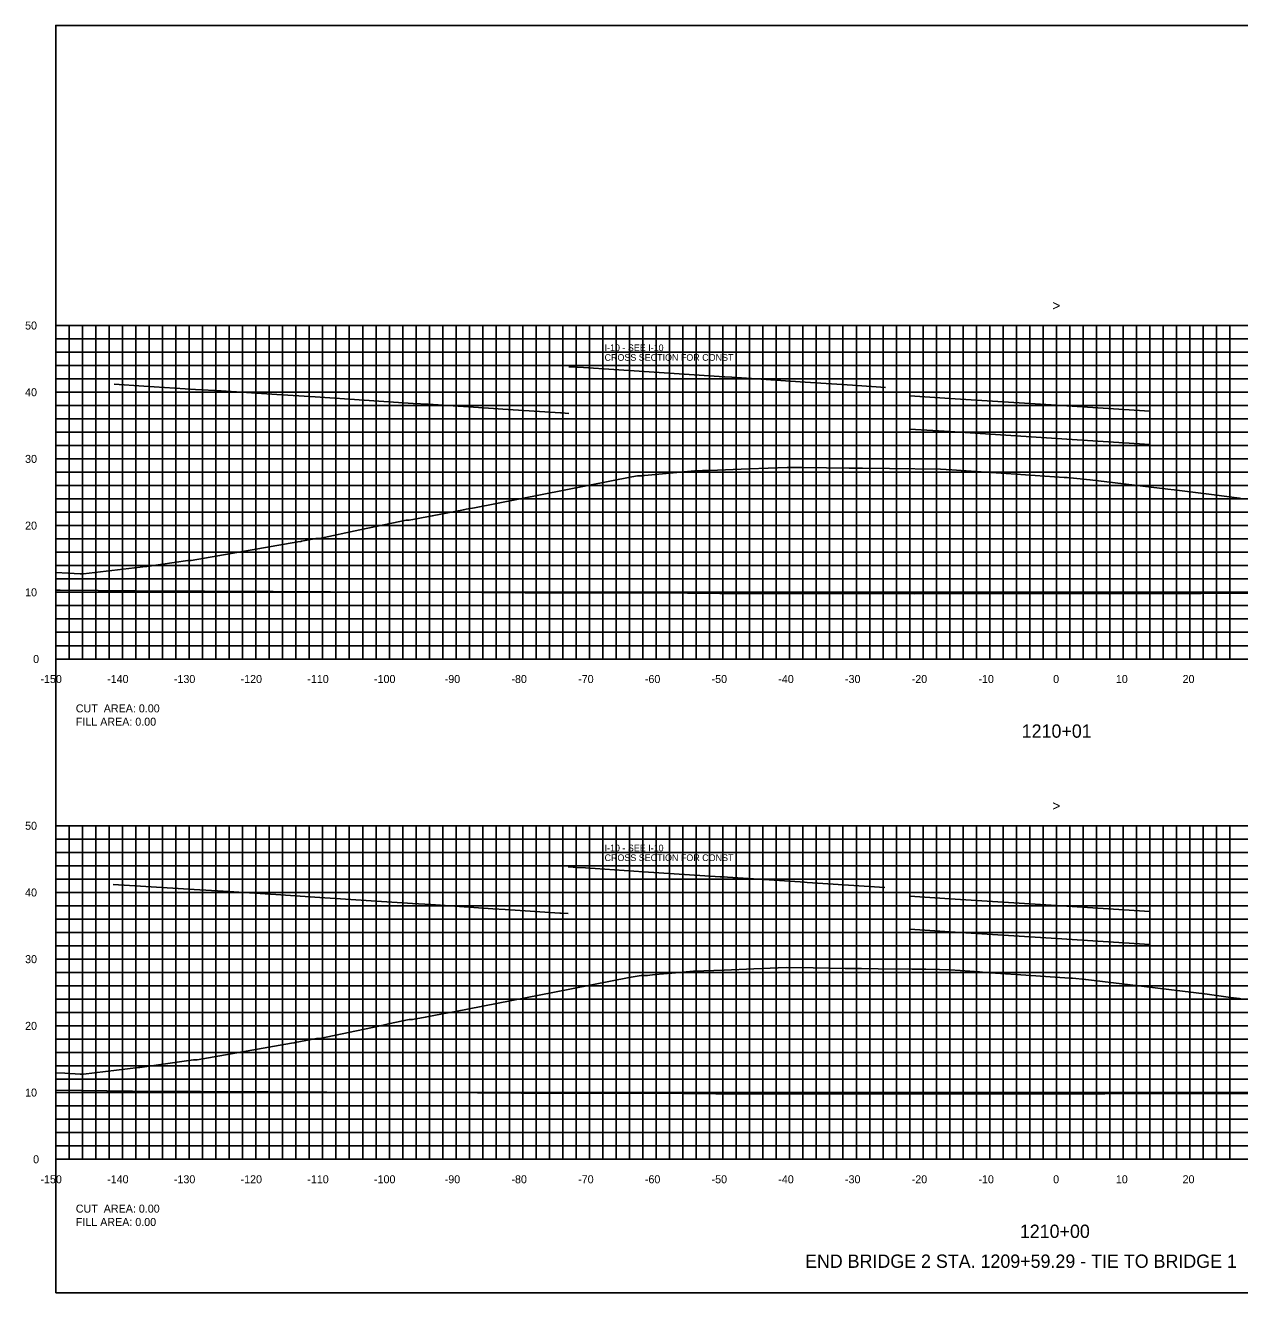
# Model space of a CAD drawing. Extents: x 1797305 to 1804485, y 245831 to 250849.
# Drawn here: x 1803836.4 to 1804018.5, y 250079.4 to 250269.4 of the extents above; entities that cross this region are included whole.
import ezdxf

# ---------------------------------------------------------------- set-up
doc = ezdxf.new("R2010")
doc.units = 0
for name, color, linetype in [('1', 7, 'Continuous'), ('10', 7, 'Continuous'), ('29', 7, 'Continuous'), ('60', 7, 'Continuous'), ('CL-CNST', 7, 'Continuous'), ('EDPV-LINE', 7, 'Continuous'), ('Level 31', 7, 'Continuous'), ('LIMT-CSLINE', 7, 'Continuous'), ('M-ROADS', 7, 'Continuous'), ('SURVEY - DRAINAGE - Area Shapes', 7, 'Continuous')]:
    doc.layers.add(name, color=color, linetype=linetype)

msp = doc.modelspace()

# ---------------------------------------------------------------- linework, layer by layer
msp.add_lwpolyline([(1803841, 250079.43), (1804141, 250079.43), (1804141, 250269.43), (1803841, 250269.43)], close=True)
at = {"layer": '29'}
for p, q in [((1803841, 250224.43), (1804141, 250224.43)), ((1803841, 250174.43), (1803841, 250224.43)), ((1803843, 250174.43), (1803843, 250224.43)), ((1803845, 250174.43), (1803845, 250224.43)), ((1803847, 250174.43), (1803847, 250224.43)), ((1803849, 250174.43), (1803849, 250224.43)), ((1803851, 250174.43), (1803851, 250224.43)), ((1803853, 250174.43), (1803853, 250224.43)), ((1803855, 250174.43), (1803855, 250224.43)), ((1803857, 250174.43), (1803857, 250224.43)), ((1803859, 250174.43), (1803859, 250224.43)), ((1803861, 250174.43), (1803861, 250224.43)), ((1803863, 250174.43), (1803863, 250224.43)), ((1803865, 250174.43), (1803865, 250224.43)), ((1803867, 250174.43), (1803867, 250224.43)), ((1803869, 250174.43), (1803869, 250224.43)), ((1803871, 250174.43), (1803871, 250224.43)), ((1803873, 250174.43), (1803873, 250224.43)), ((1803875, 250174.43), (1803875, 250224.43)), ((1803877, 250174.43), (1803877, 250224.43)), ((1803879, 250174.43), (1803879, 250224.43)), ((1803881, 250174.43), (1803881, 250224.43)), ((1803883, 250174.43), (1803883, 250224.43)), ((1803885, 250174.43), (1803885, 250224.43)), ((1803887, 250174.43), (1803887, 250224.43)), ((1803889, 250174.43), (1803889, 250224.43)), ((1803891, 250174.43), (1803891, 250224.43)), ((1803893, 250174.43), (1803893, 250224.43)), ((1803895, 250174.43), (1803895, 250224.43)), ((1803897, 250174.43), (1803897, 250224.43)), ((1803899, 250174.43), (1803899, 250224.43)), ((1803901, 250174.43), (1803901, 250224.43)), ((1803903, 250174.43), (1803903, 250224.43)), ((1803905, 250174.43), (1803905, 250224.43)), ((1803907, 250174.43), (1803907, 250224.43)), ((1803909, 250174.43), (1803909, 250224.43)), ((1803911, 250174.43), (1803911, 250224.43)), ((1803913, 250174.43), (1803913, 250224.43)), ((1803915, 250174.43), (1803915, 250224.43)), ((1803917, 250174.43), (1803917, 250224.43)), ((1803919, 250174.43), (1803919, 250224.43)), ((1803921, 250174.43), (1803921, 250224.43)), ((1803923, 250174.43), (1803923, 250224.43)), ((1803925, 250174.43), (1803925, 250224.43)), ((1803927, 250174.43), (1803927, 250224.43)), ((1803929, 250174.43), (1803929, 250224.43)), ((1803931, 250174.43), (1803931, 250224.43)), ((1803933, 250174.43), (1803933, 250224.43)), ((1803935, 250174.43), (1803935, 250224.43)), ((1803937, 250174.43), (1803937, 250224.43)), ((1803939, 250174.43), (1803939, 250224.43)), ((1803941, 250174.43), (1803941, 250224.43)), ((1803943, 250174.43), (1803943, 250224.43)), ((1803945, 250174.43), (1803945, 250224.43)), ((1803947, 250174.43), (1803947, 250224.43)), ((1803949, 250174.43), (1803949, 250224.43)), ((1803951, 250174.43), (1803951, 250224.43)), ((1803953, 250174.43), (1803953, 250224.43)), ((1803955, 250174.43), (1803955, 250224.43)), ((1803957, 250174.43), (1803957, 250224.43)), ((1803959, 250174.43), (1803959, 250224.43)), ((1803961, 250174.43), (1803961, 250224.43)), ((1803963, 250174.43), (1803963, 250224.43)), ((1803965, 250174.43), (1803965, 250224.43)), ((1803967, 250174.43), (1803967, 250224.43)), ((1803969, 250174.43), (1803969, 250224.43)), ((1803971, 250174.43), (1803971, 250224.43)), ((1803973, 250174.43), (1803973, 250224.43)), ((1803975, 250174.43), (1803975, 250224.43)), ((1803977, 250174.43), (1803977, 250224.43)), ((1803979, 250174.43), (1803979, 250224.43)), ((1803981, 250174.43), (1803981, 250224.43)), ((1803983, 250174.43), (1803983, 250224.43)), ((1803985, 250174.43), (1803985, 250224.43)), ((1803987, 250174.43), (1803987, 250224.43)), ((1803989, 250174.43), (1803989, 250224.43)), ((1803991, 250174.43), (1803991, 250224.43)), ((1803993, 250174.43), (1803993, 250224.43)), ((1803995, 250174.43), (1803995, 250224.43)), ((1803997, 250174.43), (1803997, 250224.43)), ((1803999, 250174.43), (1803999, 250224.43)), ((1804001, 250174.43), (1804001, 250224.43)), ((1804003, 250174.43), (1804003, 250224.43)), ((1804005, 250174.43), (1804005, 250224.43)), ((1804007, 250174.43), (1804007, 250224.43)), ((1804009, 250174.43), (1804009, 250224.43)), ((1804011, 250174.43), (1804011, 250224.43)), ((1804013, 250174.43), (1804013, 250224.43)), ((1804015, 250174.43), (1804015, 250224.43)), ((1804017, 250174.43), (1804017, 250224.43)), ((1803841, 250222.43), (1804141, 250222.43)), ((1803841, 250220.43), (1804141, 250220.43)), ((1803841, 250218.43), (1804141, 250218.43)), ((1803841, 250216.43), (1804141, 250216.43)), ((1803841, 250214.43), (1804141, 250214.43)), ((1803841, 250212.43), (1804141, 250212.43)), ((1803841, 250210.43), (1804141, 250210.43)), ((1803841, 250208.43), (1804141, 250208.43)), ((1803841, 250206.43), (1804141, 250206.43)), ((1803841, 250204.43), (1804141, 250204.43)), ((1803841, 250202.43), (1804141, 250202.43)), ((1803841, 250200.43), (1804141, 250200.43)), ((1803841, 250198.43), (1804141, 250198.43)), ((1803841, 250196.43), (1804141, 250196.43)), ((1803841, 250194.43), (1804141, 250194.43)), ((1803841, 250192.43), (1804141, 250192.43)), ((1803841, 250190.43), (1804141, 250190.43)), ((1803841, 250188.43), (1804141, 250188.43)), ((1803841, 250186.43), (1804141, 250186.43)), ((1803841, 250184.43), (1804141, 250184.43)), ((1803841, 250182.43), (1804141, 250182.43)), ((1803841, 250180.43), (1804141, 250180.43)), ((1803841, 250178.43), (1804141, 250178.43)), ((1803841, 250176.43), (1804141, 250176.43)), ((1803841, 250174.43), (1804141, 250174.43)), ((1803841, 250149.43), (1804141, 250149.43)), ((1803841, 250099.43), (1803841, 250149.43)), ((1803843, 250099.43), (1803843, 250149.43)), ((1803845, 250099.43), (1803845, 250149.43)), ((1803847, 250099.43), (1803847, 250149.43)), ((1803849, 250099.43), (1803849, 250149.43)), ((1803851, 250099.43), (1803851, 250149.43)), ((1803853, 250099.43), (1803853, 250149.43)), ((1803855, 250099.43), (1803855, 250149.43)), ((1803857, 250099.43), (1803857, 250149.43)), ((1803859, 250099.43), (1803859, 250149.43)), ((1803861, 250099.43), (1803861, 250149.43)), ((1803863, 250099.43), (1803863, 250149.43)), ((1803865, 250099.43), (1803865, 250149.43)), ((1803867, 250099.43), (1803867, 250149.43)), ((1803869, 250099.43), (1803869, 250149.43)), ((1803871, 250099.43), (1803871, 250149.43)), ((1803873, 250099.43), (1803873, 250149.43)), ((1803875, 250099.43), (1803875, 250149.43)), ((1803877, 250099.43), (1803877, 250149.43)), ((1803879, 250099.43), (1803879, 250149.43)), ((1803881, 250099.43), (1803881, 250149.43)), ((1803883, 250099.43), (1803883, 250149.43)), ((1803885, 250099.43), (1803885, 250149.43)), ((1803887, 250099.43), (1803887, 250149.43)), ((1803889, 250099.43), (1803889, 250149.43)), ((1803891, 250099.43), (1803891, 250149.43)), ((1803893, 250099.43), (1803893, 250149.43)), ((1803895, 250099.43), (1803895, 250149.43)), ((1803897, 250099.43), (1803897, 250149.43)), ((1803899, 250099.43), (1803899, 250149.43)), ((1803901, 250099.43), (1803901, 250149.43)), ((1803903, 250099.43), (1803903, 250149.43)), ((1803905, 250099.43), (1803905, 250149.43)), ((1803907, 250099.43), (1803907, 250149.43)), ((1803909, 250099.43), (1803909, 250149.43)), ((1803911, 250099.43), (1803911, 250149.43)), ((1803913, 250099.43), (1803913, 250149.43)), ((1803915, 250099.43), (1803915, 250149.43)), ((1803917, 250099.43), (1803917, 250149.43)), ((1803919, 250099.43), (1803919, 250149.43)), ((1803921, 250099.43), (1803921, 250149.43)), ((1803923, 250099.43), (1803923, 250149.43)), ((1803925, 250099.43), (1803925, 250149.43)), ((1803927, 250099.43), (1803927, 250149.43)), ((1803929, 250099.43), (1803929, 250149.43)), ((1803931, 250099.43), (1803931, 250149.43)), ((1803933, 250099.43), (1803933, 250149.43)), ((1803935, 250099.43), (1803935, 250149.43)), ((1803937, 250099.43), (1803937, 250149.43)), ((1803939, 250099.43), (1803939, 250149.43)), ((1803941, 250099.43), (1803941, 250149.43)), ((1803943, 250099.43), (1803943, 250149.43)), ((1803945, 250099.43), (1803945, 250149.43)), ((1803947, 250099.43), (1803947, 250149.43)), ((1803949, 250099.43), (1803949, 250149.43)), ((1803951, 250099.43), (1803951, 250149.43)), ((1803953, 250099.43), (1803953, 250149.43)), ((1803955, 250099.43), (1803955, 250149.43)), ((1803957, 250099.43), (1803957, 250149.43)), ((1803959, 250099.43), (1803959, 250149.43)), ((1803961, 250099.43), (1803961, 250149.43)), ((1803963, 250099.43), (1803963, 250149.43)), ((1803965, 250099.43), (1803965, 250149.43)), ((1803967, 250099.43), (1803967, 250149.43)), ((1803969, 250099.43), (1803969, 250149.43)), ((1803971, 250099.43), (1803971, 250149.43)), ((1803973, 250099.43), (1803973, 250149.43)), ((1803975, 250099.43), (1803975, 250149.43)), ((1803977, 250099.43), (1803977, 250149.43)), ((1803979, 250099.43), (1803979, 250149.43)), ((1803981, 250099.43), (1803981, 250149.43)), ((1803983, 250099.43), (1803983, 250149.43)), ((1803985, 250099.43), (1803985, 250149.43)), ((1803987, 250099.43), (1803987, 250149.43)), ((1803989, 250099.43), (1803989, 250149.43)), ((1803991, 250099.43), (1803991, 250149.43)), ((1803993, 250099.43), (1803993, 250149.43)), ((1803995, 250099.43), (1803995, 250149.43)), ((1803997, 250099.43), (1803997, 250149.43)), ((1803999, 250099.43), (1803999, 250149.43)), ((1804001, 250099.43), (1804001, 250149.43)), ((1804003, 250099.43), (1804003, 250149.43)), ((1804005, 250099.43), (1804005, 250149.43)), ((1804007, 250099.43), (1804007, 250149.43)), ((1804009, 250099.43), (1804009, 250149.43)), ((1804011, 250099.43), (1804011, 250149.43)), ((1804013, 250099.43), (1804013, 250149.43)), ((1804015, 250099.43), (1804015, 250149.43)), ((1804017, 250099.43), (1804017, 250149.43)), ((1803841, 250147.43), (1804141, 250147.43)), ((1803841, 250145.43), (1804141, 250145.43)), ((1803841, 250143.43), (1804141, 250143.43)), ((1803841, 250141.43), (1804141, 250141.43)), ((1803841, 250139.43), (1804141, 250139.43)), ((1803841, 250137.43), (1804141, 250137.43)), ((1803841, 250135.43), (1804141, 250135.43)), ((1803841, 250133.43), (1804141, 250133.43)), ((1803841, 250131.43), (1804141, 250131.43)), ((1803841, 250129.43), (1804141, 250129.43)), ((1803841, 250127.43), (1804141, 250127.43)), ((1803841, 250125.43), (1804141, 250125.43)), ((1803841, 250123.43), (1804141, 250123.43)), ((1803841, 250121.43), (1804141, 250121.43)), ((1803841, 250119.43), (1804141, 250119.43)), ((1803841, 250117.43), (1804141, 250117.43)), ((1803841, 250115.43), (1804141, 250115.43)), ((1803841, 250113.43), (1804141, 250113.43)), ((1803841, 250111.43), (1804141, 250111.43)), ((1803841, 250109.43), (1804141, 250109.43)), ((1803841, 250107.43), (1804141, 250107.43)), ((1803841, 250105.43), (1804141, 250105.43)), ((1803841, 250103.43), (1804141, 250103.43)), ((1803841, 250101.43), (1804141, 250101.43)), ((1803841, 250099.43), (1804141, 250099.43))]:
    msp.add_line(p, q, dxfattribs=at)
at = {"layer": 'CL-CNST'}
for points in [[(1803917.91, 250218.25), (1803918.04, 250218.24), (1803919.17, 250218.17), (1803920.09, 250218.12), (1803929.21, 250217.52), (1803941.2, 250216.74), (1803941.26, 250216.74), (1803941.31, 250216.74), (1803942.32, 250216.67), (1803953.31, 250215.95), (1803960.4, 250215.48), (1803965.36, 250215.15)], [(1803849.77, 250215.62), (1803854.19, 250215.35), (1803861.93, 250214.85), (1803865.79, 250214.62), (1803874.15, 250214.07), (1803879.88, 250213.73), (1803894.56, 250212.76), (1803896.82, 250212.63), (1803906.61, 250211.98), (1803908.03, 250211.9), (1803916.65, 250211.32), (1803916.79, 250211.32), (1803917.91, 250211.24)], [(1803969, 250213.87), (1803975, 250213.49), (1803991, 250212.47), (1804005, 250211.57)], [(1803841, 250184.77), (1803841.64, 250184.77), (1803853.04, 250184.66), (1803873.57, 250184.55), (1803882.2, 250184.48), (1803904.85, 250184.4), (1803911.36, 250184.33), (1803935.68, 250184.28), (1803940.52, 250184.25), (1803966.19, 250184.23), (1803969.68, 250184.21), (1803996.48, 250184.23), (1803998.84, 250184.22), (1804026.58, 250184.29)], [(1803917.82, 250143.26), (1803918, 250143.25), (1803919.08, 250143.18), (1803920.41, 250143.1), (1803929.12, 250142.54), (1803940.57, 250141.79), (1803941.17, 250141.76), (1803941.71, 250141.72), (1803952.57, 250141.01), (1803953.22, 250140.97), (1803953.64, 250140.94), (1803965.27, 250140.18)], [(1803849.58, 250140.63), (1803854.5, 250140.34), (1803861.75, 250139.87), (1803866.11, 250139.61), (1803873.97, 250139.1), (1803880.57, 250138.7), (1803894.48, 250137.79), (1803897.23, 250137.62), (1803906.53, 250137), (1803908.36, 250136.89), (1803916.57, 250136.35), (1803916.75, 250136.34), (1803917.82, 250136.27)], [(1803969, 250138.87), (1803975, 250138.49), (1803991, 250137.47), (1804005, 250136.58)], [(1803841, 250109.78), (1803852.48, 250109.66), (1803872.91, 250109.56), (1803881.64, 250109.49), (1803904.2, 250109.4), (1803910.8, 250109.34), (1803935.04, 250109.29), (1803939.95, 250109.26), (1803965.57, 250109.24), (1803969.11, 250109.21), (1803995.85, 250109.24), (1803998.27, 250109.22), (1804025.96, 250109.29)]]:
    msp.add_lwpolyline(points, dxfattribs=at)
at = {"layer": 'Level 31'}
for p, q in [((1803840.94, 250224.43), (1803841, 250224.43)), ((1803841, 250174.43), (1803841, 250224.43)), ((1803840.94, 250214.43), (1803841, 250214.43)), ((1803840.94, 250204.43), (1803841, 250204.43)), ((1803840.94, 250194.43), (1803841, 250194.43)), ((1803840.94, 250184.43), (1803841, 250184.43)), ((1803840.94, 250174.43), (1803841, 250174.43)), ((1803841, 250174.43), (1804141, 250174.43)), ((1803841, 250174.37), (1803841, 250174.43)), ((1803851, 250174.37), (1803851, 250174.43)), ((1803861, 250174.37), (1803861, 250174.43)), ((1803871, 250174.37), (1803871, 250174.43)), ((1803881, 250174.37), (1803881, 250174.43)), ((1803891, 250174.37), (1803891, 250174.43)), ((1803901, 250174.37), (1803901, 250174.43)), ((1803911, 250174.37), (1803911, 250174.43)), ((1803921, 250174.37), (1803921, 250174.43)), ((1803931, 250174.37), (1803931, 250174.43)), ((1803941, 250174.37), (1803941, 250174.43)), ((1803951, 250174.37), (1803951, 250174.43)), ((1803961, 250174.37), (1803961, 250174.43)), ((1803971, 250174.37), (1803971, 250174.43)), ((1803981, 250174.37), (1803981, 250174.43)), ((1803991, 250174.37), (1803991, 250174.43)), ((1804001, 250174.37), (1804001, 250174.43)), ((1804011, 250174.37), (1804011, 250174.43)), ((1803840.94, 250149.43), (1803841, 250149.43)), ((1803841, 250099.43), (1803841, 250149.43)), ((1803840.94, 250139.43), (1803841, 250139.43)), ((1803840.94, 250129.43), (1803841, 250129.43)), ((1803840.94, 250119.43), (1803841, 250119.43)), ((1803840.94, 250109.43), (1803841, 250109.43)), ((1803840.94, 250099.43), (1803841, 250099.43)), ((1803841, 250099.43), (1804141, 250099.43)), ((1803841, 250099.37), (1803841, 250099.43)), ((1803851, 250099.37), (1803851, 250099.43)), ((1803861, 250099.37), (1803861, 250099.43)), ((1803871, 250099.37), (1803871, 250099.43)), ((1803881, 250099.37), (1803881, 250099.43)), ((1803891, 250099.37), (1803891, 250099.43)), ((1803901, 250099.37), (1803901, 250099.43)), ((1803911, 250099.37), (1803911, 250099.43)), ((1803921, 250099.37), (1803921, 250099.43)), ((1803931, 250099.37), (1803931, 250099.43)), ((1803941, 250099.37), (1803941, 250099.43)), ((1803951, 250099.37), (1803951, 250099.43)), ((1803961, 250099.37), (1803961, 250099.43)), ((1803971, 250099.37), (1803971, 250099.43)), ((1803981, 250099.37), (1803981, 250099.43)), ((1803991, 250099.37), (1803991, 250099.43)), ((1804001, 250099.37), (1804001, 250099.43)), ((1804011, 250099.37), (1804011, 250099.43))]:
    msp.add_line(p, q, dxfattribs=at)
at = {"layer": 'M-ROADS'}
for points in [[(1803841, 250187.39), (1803842.83, 250187.32), (1803844.67, 250187.21), (1803844.83, 250187.21), (1803845.17, 250187.21), (1803854.5, 250188.3), (1803854.65, 250188.32), (1803860.77, 250189.2), (1803861.15, 250189.2), (1803861.3, 250189.2), (1803877.3, 250192), (1803877.74, 250192.07), (1803877.84, 250192.09), (1803880.02, 250192.52), (1803880.48, 250192.52), (1803880.53, 250192.52), (1803886.55, 250193.78), (1803887.28, 250193.93), (1803888.04, 250194.1), (1803893.53, 250195.25), (1803893.97, 250195.25), (1803897.43, 250195.88), (1803902.09, 250196.81), (1803902.51, 250196.88), (1803903.78, 250197.12), (1803927.33, 250201.72), (1803928.2, 250201.88), (1803928.34, 250201.91), (1803928.37, 250201.91), (1803928.89, 250201.91), (1803928.93, 250201.92), (1803929, 250201.92), (1803929.25, 250201.94), (1803936.8, 250202.62), (1803937.92, 250202.67), (1803939.01, 250202.71), (1803944.92, 250202.94), (1803950.62, 250203.15), (1803951.75, 250203.14), (1803953.09, 250203.12), (1803956.55, 250203.08), (1803959.93, 250203.05), (1803960.6, 250203.04), (1803961.9, 250203.02), (1803965.97, 250202.98), (1803973.62, 250202.89), (1803975.29, 250202.79), (1803976.71, 250202.71), (1803983.47, 250202.23), (1803992.17, 250201.65), (1803992.59, 250201.65), (1803995.98, 250201.28), (1803996.06, 250201.29), (1804007.7, 250199.89), (1804008.64, 250199.78), (1804014.25, 250199.09), (1804018.01, 250198.58), (1804018.04, 250198.58), (1804018.41, 250198.54), (1804018.42, 250198.54), (1804018.63, 250198.51)], [(1803841, 250112.39), (1803842.35, 250112.34), (1803844.64, 250112.2), (1803844.83, 250112.2), (1803845.14, 250112.2), (1803853.42, 250113.18), (1803853.62, 250113.2), (1803861.65, 250114.35), (1803861.99, 250114.35), (1803862.17, 250114.35), (1803876.33, 250116.82), (1803876.72, 250116.89), (1803876.87, 250116.92), (1803880.08, 250117.54), (1803880.51, 250117.55), (1803880.58, 250117.55), (1803889.4, 250119.39), (1803890.46, 250119.62), (1803890.89, 250119.72), (1803893.97, 250120.36), (1803894.45, 250120.36), (1803896.37, 250120.71), (1803898.96, 250121.23), (1803899.2, 250121.27), (1803900.65, 250121.54), (1803915.76, 250124.49), (1803926.94, 250126.67), (1803928.76, 250126.96), (1803929.23, 250127), (1803929.68, 250127), (1803930.06, 250127.04), (1803930.84, 250127.11), (1803933.34, 250127.33), (1803936.61, 250127.62), (1803941.18, 250127.8), (1803945.62, 250127.97), (1803948.09, 250128.07), (1803950.47, 250128.16), (1803954.52, 250128.11), (1803959.33, 250128.05), (1803960.29, 250128.04), (1803961.75, 250128.03), (1803964.27, 250128), (1803969.38, 250127.94), (1803971.43, 250127.92), (1803973.47, 250127.9), (1803974.99, 250127.81), (1803976.56, 250127.72), (1803979.47, 250127.51), (1803980.34, 250127.45), (1803987.9, 250126.91), (1803992.93, 250126.58), (1803993.4, 250126.57), (1803995.34, 250126.36), (1803995.39, 250126.36), (1804002.07, 250125.57), (1804003.73, 250125.37), (1804013.6, 250124.16), (1804017.1, 250123.68), (1804017.16, 250123.68), (1804017.97, 250123.58), (1804017.99, 250123.58), (1804018.45, 250123.52), (1804018.45, 250123.52), (1804018.61, 250123.5)]]:
    msp.add_lwpolyline(points, dxfattribs=at)
at = {"layer": 'SURVEY - DRAINAGE - Area Shapes'}
for points in [[(1804005, 250206.61), (1804005, 250211.57), (1803991, 250212.47), (1803975, 250213.49), (1803969, 250213.87), (1803969, 250208.91), (1803975, 250208.53), (1803991, 250207.51)], [(1804005, 250131.62), (1804005, 250136.58), (1803991, 250137.47), (1803975, 250138.49), (1803969, 250138.87), (1803969, 250133.91), (1803975, 250133.53), (1803991, 250132.51)]]:
    msp.add_lwpolyline(points, close=True, dxfattribs=at)

# ---------------------------------------------------------------- texts
at = {"layer": '1'}
for s, p in [('1210+01', (1803985.79, 250162.63)), ('1210+00', (1803985.51, 250087.63)), ('END BRIDGE 2 STA. 1209+59.29 - TIE TO BRIDGE 1', (1803953.31, 250083.15))]:
    msp.add_text(s, height=2, dxfattribs=at).set_placement(p)
at = {"layer": '10'}
for s, p in [('-150', (1803838.7, 250170.83)), ('-140', (1803848.7, 250170.83)), ('-130', (1803858.7, 250170.83)), ('-120', (1803868.7, 250170.83)), ('-110', (1803878.7, 250170.83)), ('-100', (1803888.7, 250170.83)), ('-90', (1803899.3, 250170.83)), ('-80', (1803909.3, 250170.83)), ('-70', (1803919.3, 250170.83)), ('-60', (1803929.3, 250170.83)), ('-50', (1803939.3, 250170.83)), ('-40', (1803949.3, 250170.83)), ('-30', (1803959.3, 250170.83)), ('-20', (1803969.3, 250170.83)), ('-10', (1803979.3, 250170.83)), ('0', (1803990.5, 250170.83)), ('10', (1803999.9, 250170.83)), ('20', (1804009.9, 250170.83)), ('-150', (1803838.7, 250095.83)), ('-140', (1803848.7, 250095.83)), ('-130', (1803858.7, 250095.83)), ('-120', (1803868.7, 250095.83)), ('-110', (1803878.7, 250095.83)), ('-100', (1803888.7, 250095.83)), ('-90', (1803899.3, 250095.83)), ('-80', (1803909.3, 250095.83)), ('-70', (1803919.3, 250095.83)), ('-60', (1803929.3, 250095.83)), ('-50', (1803939.3, 250095.83)), ('-40', (1803949.3, 250095.83)), ('-30', (1803959.3, 250095.83)), ('-20', (1803969.3, 250095.83)), ('-10', (1803979.3, 250095.83)), ('0', (1803990.5, 250095.83)), ('10', (1803999.9, 250095.83)), ('20', (1804009.9, 250095.83))]:
    msp.add_text(s, height=1.2, dxfattribs=at).set_placement(p)
at = {"layer": '60'}
for s, p in [('50', (1803836.4, 250223.83)), ('40', (1803836.4, 250213.83)), ('30', (1803836.4, 250203.83)), ('20', (1803836.4, 250193.83)), ('10', (1803836.4, 250183.83)), ('0', (1803837.6, 250173.83)), ('50', (1803836.4, 250148.83)), ('40', (1803836.4, 250138.83)), ('30', (1803836.4, 250128.83)), ('20', (1803836.4, 250118.83)), ('10', (1803836.4, 250108.83)), ('0', (1803837.6, 250098.83))]:
    msp.add_text(s, height=1.2, dxfattribs=at).set_placement(p)
at = {"layer": 'EDPV-LINE'}
for s, p in [('CUT  AREA: 0.00', (1803844, 250166.43)), ('FILL AREA: 0.00', (1803844, 250164.43)), ('CUT  AREA: 0.00', (1803844, 250091.43)), ('FILL AREA: 0.00', (1803844, 250089.43))]:
    msp.add_text(s, height=1.2, dxfattribs=at).set_placement(p)
at = {"layer": 'Level 31'}
for s, height, p in [('>', 1.5, (1803990.39, 250226.68)), ('-', 0.0001, (1803841, 250174.43)), ('>', 1.5, (1803990.39, 250151.68)), ('-', 0.0001, (1803841, 250099.43))]:
    msp.add_text(s, height=height, dxfattribs=at).set_placement(p)
at = {"layer": 'LIMT-CSLINE'}
for s, p in [('I-10 - SEE I-10', (1803923.26, 250220.59)), ('CROSS SECTION FOR CONST ', (1803923.26, 250219.14)), ('I-10 - SEE I-10', (1803923.26, 250145.59)), ('CROSS SECTION FOR CONST ', (1803923.26, 250144.14))]:
    msp.add_text(s, height=1, dxfattribs=at).set_placement(p)

doc.saveas('drawing.dxf')
